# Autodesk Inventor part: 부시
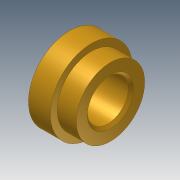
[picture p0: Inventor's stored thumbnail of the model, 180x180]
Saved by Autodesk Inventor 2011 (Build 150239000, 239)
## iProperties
Created: 2011-04
Part Number: 부시
Document SubType Name: Modeling
Designer: 한국산업디자인학원 [http://gmhk.co.kr]
Density: 1 g/cm^3
Author: pww
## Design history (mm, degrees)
sketch "스케치1"
  geometry: L1 (0, 0)-(15, 0); L2 (0, 7.5)-(15, 7.5); L3 (15, 7.5)-(15, 12.5); L4 (15, 12.5)-(8, 12.5); L5 (8, 12.5)-(8, 15); L6 (8, 15)-(0, 15); L7 (0, 15)-(0, 7.5)
  constraints: 14 end point, 4 parallel, 2 vertical alignment, 1 horizontal, 1 perpendicular, 1 vertical
  dimensions: "d0" = 15 distance of L1.start L1.end; "d1" = 15 diameter of L2 L1; "d2" = 25 diameter of L4 L1; "d3" = 8 distance of L5.end L6.end; "d4" = 30 diameter of L6 L1
revolve "회전1" sketch "스케치1" stored, may be unused: angle "d5" = 90 deg
chamfer "모따기1" distance "d6" = 1; stored, may be unused: second distance "d7" = 2, angle "d8" = 45 deg
node "솔리드1"
